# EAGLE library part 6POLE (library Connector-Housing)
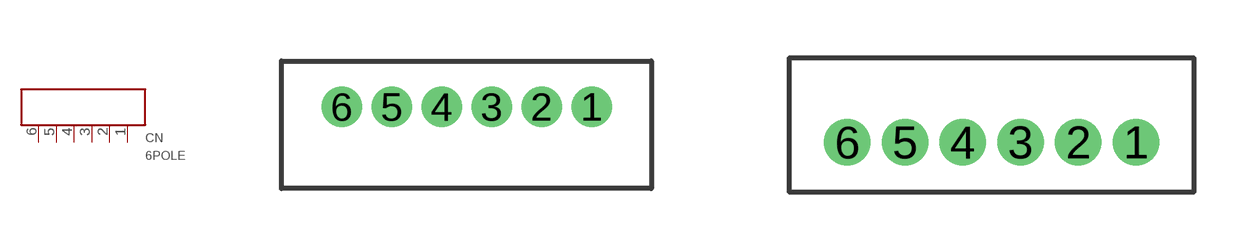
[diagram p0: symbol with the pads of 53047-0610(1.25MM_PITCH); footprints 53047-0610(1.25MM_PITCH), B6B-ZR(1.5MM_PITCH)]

Designator prefix CN

## 6POLE-53047  [53047-0610(1.25MM_PITCH)]
1  P$6
2  P$5
3  P$4
4  P$3
5  P$2
6  P$1

## 6POLE-ZR  [B6B-ZR(1.5MM_PITCH)]
Pads as for 53047-0610(1.25MM_PITCH)

## 6POLE-PASK  [B06B-PASK(2MM_PITCH)]
Pads as for 53047-0610(1.25MM_PITCH)

## Footprint 53047-0610(1.25MM_PITCH) (pad centres in mm)
53047-0610 1.25mm pitch , 6pole connector Producted by molex.
drill 0.5 round: 1 3.135,0; 2 1.885,0; 3 0.635,0; 4 -0.615,0; 5 -1.865,0; 6 -3.115,0

## Footprint B6B-ZR(1.5MM_PITCH) (pad centres in mm)
B6B-ZR _ZH series 1.5mm pitch connector Producted by JST.
drill 0.7 round: 1 3.75,0; 2 2.25,0; 3 0.75,0; 4 -0.75,0; 5 -2.25,0; 6 -3.75,0

## Footprint B06B-PASK(2MM_PITCH) (pad centres in mm)
B06B-PASK _PA series 2.0mm pitch connector Producted by JST.
drill 1 round: 1 5,0; 6 -5,0
drill 0.8 round: 2 3,0; 3 1,0; 4 -1,0; 5 -3,0
hole 0.9 at 6.5,1.7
